Omron CX-Programmer project 新工程 (CX-Programmer 9.50)

# PLC 新PLC1: CP1E NA

## Global symbols (name address type ; comment)
W0.00 BOOL  ; 报警画面弹出
W0.01 BOOL  ; 关闭报警画面
W1.01 BOOL  ; 关闭报警弹出
启动报警弹出 W1.00 BOOL

## Program 新程序1 (cyclic task 0)

### Section 段1

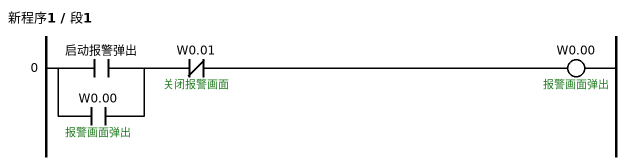
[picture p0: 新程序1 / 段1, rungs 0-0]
; rung 0
LD 启动报警弹出
OR W0.00  ; 报警画面弹出
ANDNOT W0.01  ; 关闭报警画面
OUT W0.00  ; 报警画面弹出

### Section END
; rung 0
END(001)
